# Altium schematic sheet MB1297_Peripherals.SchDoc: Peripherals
size A4; Date: Not used; ApprovedBy: Not used; CheckedBy: Not used; Author: Not used; CompanyName: STMicroelectronics; DrawnBy: Not used; Engineer: Not used; Organization: Not used; Address1: Not used; Address2: Not used; Address3: Not used; Address4: Not used; DocumentNumber: Not used; Revision: Not used; SheetNumber: 11; SheetTotal: 12
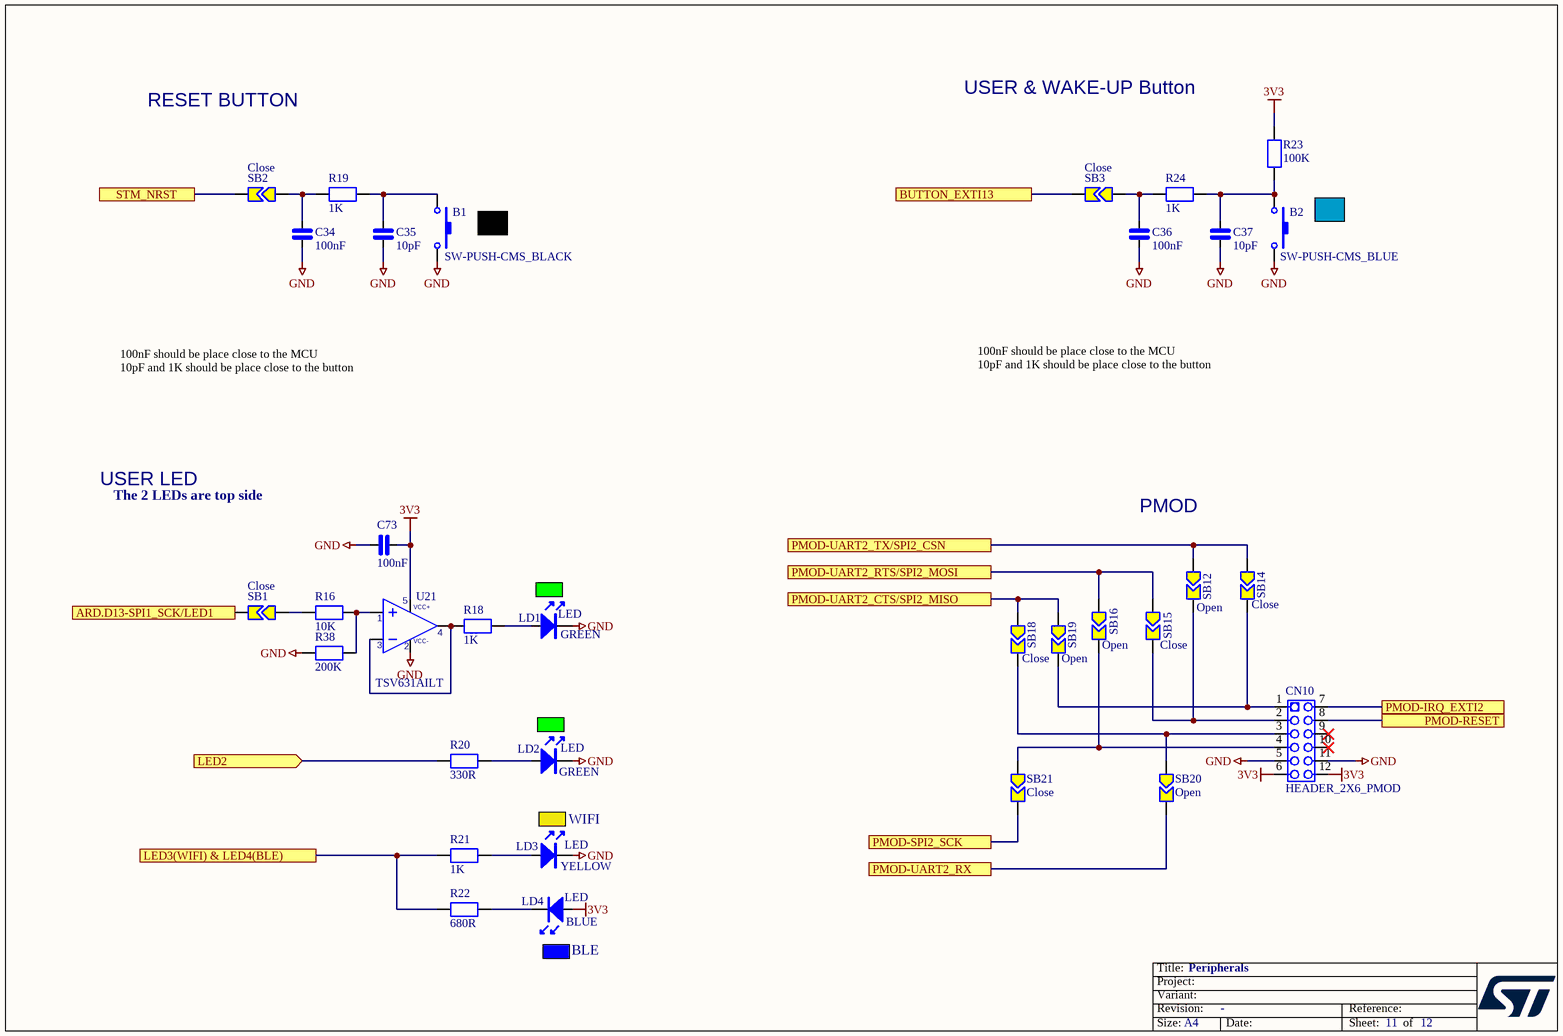
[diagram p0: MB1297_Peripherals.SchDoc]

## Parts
B1  SW-PUSH-CMS_BLACK  [SWI_WEALTHMETAL_TD-0341_4P - BACK]
B2  SW-PUSH-CMS_BLUE  [SWI_WEALTHMETAL_TD-0341_4P - BLUE]
C34  100nF  [0402]
C35  10pF  [0402]
C36  100nF  [0402]
C37  10pF  [0402]
C73  100nF  [0402]
CN10  HEADER_2X6_PMOD  [Header F 2x6x2.54 TH H PMOD]
LD1  LED  Color: GREEN  [0603_LED_GREEN]
LD2  LED  Color: GREEN  [0603_LED_GREEN]
LD3  LED  Color: YELLOW  [0603_LED_Yellow]
LD4  LED  Color: BLUE  [0603_LED_Blue]
R16  10K  [0402]
R18  1K  [0402]
R19  1K  [0402]
R20  330R  [0402]
R21  1K  [0402]
R22  680R  [0402]
R23  100K  [0402]
R24  1K  [0402]
R38  200K  [0402]
SB1  Close  [SB]
SB2  Close  [SB]
SB3  Close  [SB]
SB12  Open  [SB]
SB14  Close  [SB]
SB15  Close  [SB]
SB16  Open  [SB]
SB18  Close  [SB]
SB19  Open  [SB]
SB20  Open  [SB]
SB21  Close  [SB]
U21  TSV631AILT  [SOT23-5]

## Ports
ARD.D13-SPI1_SCK/LED1, BUTTON_EXTI13, LED2 (in), LED3(WIFI) & LED4(BLE), PMOD-IRQ_EXTI2, PMOD-RESET, PMOD-SPI2_SCK, PMOD-UART2_CTS/SPI2_MISO, PMOD-UART2_RTS/SPI2_MOSI, PMOD-UART2_RX, PMOD-UART2_TX/SPI2_CSN, STM_NRST

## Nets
3V3: C73.1 CN10.6 CN10.12 LD4.A R23.2 U21.5(V+)
GND: B1.2 B2.2 C34.2 C35.2 C36.2 C37.2 C73.2 CN10.5 CN10.11 LD1.K LD2.K LD3.K R38.1 U21.2(V-)
ARD.D13-SPI1_SCK/LED1: SB1.1 ; port ARD.D13-SPI1_SCK/LED1
BUTTON_EXTI13: SB3.1 ; port BUTTON_EXTI13
LED2: R20.1 ; port LED2
LED3(WIFI) & LED4(BLE): R21.1 R22.1 ; port LED3(WIFI) & LED4(BLE)
PMOD-IRQ_EXTI2: CN10.7 ; port PMOD-IRQ_EXTI2
PMOD-RESET: CN10.8 ; port PMOD-RESET
PMOD-SPI2_SCK: SB21.1 ; port PMOD-SPI2_SCK
PMOD-UART2_CTS/SPI2_MISO: SB18.2 SB19.2 ; port PMOD-UART2_CTS/SPI2_MISO
PMOD-UART2_RTS/SPI2_MOSI: SB15.2 SB16.2 ; port PMOD-UART2_RTS/SPI2_MOSI
PMOD-UART2_RX: SB20.1 ; port PMOD-UART2_RX
PMOD-UART2_TX/SPI2_CSN: SB12.2 SB14.2 ; port PMOD-UART2_TX/SPI2_CSN
STM_NRST: SB2.1 ; port STM_NRST
NetB1_1: B1.1 C35.1 R19.2
NetB2_1: B2.1 C37.1 R23.1 R24.2
NetC34_1: C34.1 R19.1 SB2.2
NetC36_1: C36.1 R24.1 SB3.2
NetCN10_1: CN10.1 SB14.1 SB19.1
NetCN10_2: CN10.2 SB12.1 SB15.1
NetCN10_3: CN10.3 SB18.1 SB20.2
NetCN10_4: CN10.4 SB16.1 SB21.2
NetLD1_A: LD1.A R18.2
NetLD2_A: LD2.A R20.2
NetLD3_A: LD3.A R21.2
NetLD4_K: LD4.K R22.2
NetR16_1: R16.1 SB1.2
NetR16_2: R16.2 R38.2 U21.1(IN+)
NetR18_1: R18.1 U21.3(IN-) U21.4(OUT)

Not connected (* = marked no-connect by the designer): CN10 9* 10*

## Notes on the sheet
- RESET BUTTON
- USER & WAKE-UP Button
- 100nF should be place close to the MCU
  10pF and 1K should be place close to the button
- USER LED
- The 2 LEDs are top side
- PMOD
- (near LD3) WIFI
- (near LD4) BLE

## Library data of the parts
B1 B2 = SW-PB_2: Push-button SMD; Order code RS: 102-412
C34-C37 C73 = CAP_NPOL: Capacitor_not polarized
CN10 = HEADER_2X6_PMOD: PMOD Connector Warning Specific Pinout
LD1-LD4 = LED: Light-Emitting Diode
R16 R18-R24 R38 = RES: Resistor
SB1-SB3 SB12 SB14-SB16 SB18-SB21 = Strap2: Solder Jumper; Solder: YES
U21 = TSV631AILT: TSV631AILT  Rail-to-rail input/output, 60 µA, 880 kHz, 5 V CMOS  operational amplifiers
